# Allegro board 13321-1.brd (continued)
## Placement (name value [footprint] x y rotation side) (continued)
PG4404  GAP-CLOSE-PWR-3-GP  [GAP-CLOSE-PWR-3]  73.41 26.76 180 bottom
PG4405  GAP-CLOSE-PWR-3-GP  [GAP-CLOSE-PWR-3]  76.71 26.76 0 bottom
PG4406  GAP-CLOSE-PWR-3-GP  [GAP-CLOSE-PWR-3]  44.7 26.76 90 bottom
PG4407  GAP-CLOSE-PWR-3-GP  [GAP-CLOSE-PWR-3]  73.41 25.62 180 bottom
PG4408  GAP-CLOSE-PWR-3-GP  [GAP-CLOSE-PWR-3]  42.16 7.71 270 top
PG4532  GAP-CLOSE-PWR-3-GP  [GAP-CLOSE-PWR-3]  24.38 86.71 270 bottom
PG4535  GAP-CLOSE-PWR-3-GP  [GAP-CLOSE-PWR-3]  39.12 87.72 0 bottom
PG4707  GAP-CLOSE-PWR-3-GP  [GAP-CLOSE-PWR-3]  50.67 63.09 90 bottom
PG4708  GAP-CLOSE-PWR-3-GP  [GAP-CLOSE-PWR-3]  50.67 58.26 270 bottom
PG4801  GAP-CLOSE-PWR-3-GP  [GAP-CLOSE-PWR-3]  53.72 83.91 0 bottom
PG4901  -  [GAP-CLOSE-PWR]  141.35 39.34 90 bottom
PG4902  -  [GAP-CLOSE-PWR]  137.67 57.12 90 bottom
PG4903  -  [GAP-CLOSE-PWR]  139.83 39.34 90 bottom
PG4904  -  [GAP-CLOSE-PWR]  139.95 57.12 90 bottom
PG4905  -  [GAP-CLOSE-PWR]  140.72 57.12 90 bottom
PG4906  -  [GAP-CLOSE-PWR]  140.59 39.34 90 bottom
PG4907  -  [GAP-CLOSE-PWR]  142.11 39.34 90 bottom
PG4908  -  [GAP-CLOSE-PWR]  139.19 57.12 90 bottom
PG4909  -  [GAP-CLOSE-PWR]  138.43 57.12 90 bottom
PG4917  -  [GAP-CLOSE-PWR]  135.51 76.42 90 top
PG4918  -  [GAP-CLOSE-PWR]  134.75 76.42 90 top
PG5101  -  [GAP-CLOSE-PWR]  56.64 89.12 90 bottom
PL4401  COIL-2D2UH-11-GP  [L11510030H158]  63.25 27.91 270 bottom
PL4501  IND-3D3UH-57GP  [L736630H119]  28.45 81.37 0 bottom
PL4503  COIL-4D7UH-33-GP  [L7066-1830-UH119]  37.47 81.25 180 bottom
PL4701  IND-D22UH-46-GP  [L109100-2430-UH158]  50.67 60.67 180 bottom
PL4801  IND-D68UH-40-GP  [L4947-1015H119]  52.83 83.91 270 bottom
PL4901  IND-D68UH-40-GP  [L4947-1015H119]  139.7 49.88 0 bottom
PQ4201  FDV301N-NL-GP  [SOT23DGS2D4H44]  37.72 97.25 270 top
PQ4202  CH3904PT-GP  [SOT23CBE2D6H46]  37.72 101.06 90 top
PQ4401  2N7002K-2-GP  [SOT23DGS2D4H44]  27.69 6.06 180 top
PQ4405  2N7002KDW-GP  [SOT-363H44]  38.48 4.54 90 top
PQ4406  2N7002K-2-GP  [SOT23DGS2D4H44]  40.64 10.38 180 bottom
PQ4407  2N7002KDW-GP  [SOT-363H44]  40.16 25.83 270 top
PQ4408  MMBT3906-4-GP  [SOT23CBE2D4H44]  23.5 6.06 180 top
PQ4411  2N7002KDW-GP  [SOT-363H44]  33.4 3.52 90 bottom
PQ4413  2N7002KDW-GP  [SOT-363H44]  38.48 4.54 270 bottom
PR4202  15KR2F-GP  [R402H16]  35.31 99.36 180 top
PR4203  10KR2J-3-GP  [R402H16]  35.31 96.61 180 top
PR4204  2K2R2J-2-GP  [R402H16]  42.29 98.52 270 top
PR4205  33R2J-2-GP  [R402H16]  41.91 97.12 180 top
PR4206  33R2J-2-GP  [R402H16]  41.02 97.12 0 top
PR4207  240KR3-GP  [R603H22]  44.32 29.69 180 bottom
PR4208  47KR3J-L-GP  [R603H22]  45.72 29.69 0 bottom
PR4209  100KR2J-1-GP  [R402H16]  35.31 102.08 0 top
PR4217  0R0603-PAD-2-GP-U  [0R0603-PAD-1-U]  17.27 92.8 180 top
PR4401  182KR2F-GP  [R402H16]  31.88 5.56 270 bottom
PR4402  75KR2F-GP  [R402H16]  31.5 8.35 180 bottom
PR4403  10R5J-GP  [R805H24]  35.56 18.26 90 top
PR4404  120KR2J-GP  [R402H16]  42.39 5.3 0 bottom
PR4405  100KR2F-L1-GP  [R402H16]  35.94 7.59 0 top
PR4406  0R0402-PAD-2-GP  [0R0402-PAD-1]  43.18 15.08 180 bottom
PR4407  6D8R2F-GP  [R402H16]  75.06 27.53 90 top
PR4408  20R3F-L-GP  [R603H22]  48.03 12.11 270 top
PR4409  1KR2F-3-GP  [R402H16]  46.99 13.18 90 top
PR4410  100KR2J-1-GP  [R402H16]  41.5 5.3 180 bottom
PR4411  47KR2F-GP  [R402H16]  36.96 11.52 0 top
PR4412  100KR2J-1-GP  [R402H16]  39.37 7.21 90 bottom
PR4413  0R2J-2-GP  [R402H16]  44.2 7.59 180 top
PR4414  3K3R2J-3-GP  [R402H16]  42.55 5.3 180 top
PR4415  0R2J-2-GP  [R402H16]  45.09 7.59 180 top
PR4416  100KR2J-1-GP  [R402H16]  26.29 8.48 270 top
PR4417  0R0402-PAD-2-GP  [0R0402-PAD-1]  47.75 15.08 90 top
PR4418  3K3R6J-GP  [R1206H28]  39.75 22.07 180 top
PR4419  0R2J-2-GP  [R402H16]  29.08 9.24 0 top
PR4420  75KR2F-GP  [R402H16]  37.59 2.51 270 bottom
PR4421  0R2J-2-GP  [R402H16]  36.96 15.08 0 top
PR4422  1M8R2J-L-GP  [R402H16]  31.75 3.14 0 top
PR4423  10KR2F-2-GP  [R402H16]  42.42 23.97 0 top
PR4424  100KR2F-L1-GP  [R402H16]  44.7 10.13 0 bottom
PR4425  0R3J-0-U-GP  [R603H22]  42.16 18.64 180 top
PR4426  D01R3721F-GP-U  [R3720H40]  45.21 24.61 270 bottom
PR4427  2D2R5F-2-GP  [R805H24]  54.36 28.54 270 top
PR4428  150KR2F-L-GP  [R402H16]  32.38 8.35 180 bottom
PR4429  100KR2J-1-GP  [R402H16]  38.35 9.37 180 bottom
PR4430  0R0402-PAD-2-GP  [0R0402-PAD-1]  37.47 12.79 270 top
PR4431  100KR2F-L1-GP  [R402H16]  43.81 10.13 0 bottom
PR4432  3K3R2J-3-GP  [R402H16]  43.43 5.3 180 top
PR4433  1MR2J-1-GP  [R402H16]  21.21 7.46 180 top
PR4434  0R0402-PAD-2-GP  [0R0402-PAD-1]  37.59 7.59 0 top
PR4435  100KR2J-1-GP  [R402H16]  42.8 22.57 270 top
PR4436  220KR2F-GP  [R402H16]  35.94 6.83 180 bottom
PR4437  100KR2J-1-GP  [R402H16]  35.05 6.83 0 bottom
PR4438  0R0402-PAD-2-GP  [0R0402-PAD-1]  47.75 16.1 90 top
PR4439  4K02R2F-GP  [R402H16]  37.47 13.68 90 top
PR4440  120KR2J-GP  [R402H16]  30.61 12.29 270 top
PR4441  100KR2F-L1-GP  [R402H16]  30.61 14.06 90 top
PR4442  412KR2F-GP  [R402H16]  32.38 14.06 270 top
PR4443  D01R2512F-3-GP  [R2512H32]  75.06 26.26 270 bottom
PR4444  287KR2F-GP  [R402H16]  36.58 9.62 90 top
PR4445  33KR2F-GP  [R402H16]  46.48 10.13 180 bottom
PR4446  20KR2F-L-GP  [R402H16]  77.72 30.57 180 top
PR4447  180KR2F-GP  [R402H16]  32.38 12.29 90 top
PR4448  0R2J-2-GP  [R402H16]  73.79 27.15 180 top
PR4449  100KR2J-1-GP  [R402H16]  46.48 11.91 180 bottom
PR4450  10KR2F-2-GP  [R402H16]  34.8 4.54 180 top
PR4451  680KR2F-GP  [R402H16]  44.83 3.52 90 top
PR4452  0R2J-2-GP  [R402H16]  77.72 28.8 180 top
PR4453  100KR2F-L1-GP  [R402H16]  28.32 12.29 90 top
PR4454  10R2F-L-GP  [R402H14]  76.33 27.15 180 top
PR4455  0R0402-PAD-2-GP  [0R0402-PAD-1]  41.53 5.3 0 top
PR4456  0R2J-2-GP  [R402H16]  36.83 10 0 bottom
PR4457  0R2J-2-GP  [R402H16]  41.78 3.02 0 bottom
PR4458  0R0402-PAD-2-GP  [0R0402-PAD-1]  32.77 13.3 180 bottom
PR4460  100KR2F-L1-GP  [R402H16]  29.08 11.02 0 top
PR4461  100KR2F-L1-GP  [R402H16]  30.61 13.18 90 top
PR4462  0R0402-PAD-2-GP  [0R0402-PAD-1]  42.93 3.52 90 top
PR4463  0R2J-2-GP  [R402H16]  41.15 3.52 90 top
PR4464  0R2J-2-GP  [R402H16]  26.8 3.65 90 top
PR4465  316KR2F-GP  [R402H16]  32.38 13.18 270 top
PR4466  0R0402-PAD-2-GP  [0R0402-PAD-1]  29.46 2.76 270 top
PR4467  0R0402-PAD-2-GP  [0R0402-PAD-1]  40.26 7.59 0 top
PR4468  150KR2F-L-GP  [R402H16]  45.59 10.13 0 bottom
PR4469  0R0402-PAD-2-GP  [0R0402-PAD-1]  41.15 7.59 180 top
PR4470  100KR2J-1-GP  [R402H16]  47.75 18.13 0 top
PR4471  100KR2J-1-GP  [R402H16]  49.02 17.87 90 top
PR4501  0R2J-2-GP  [R402H16]  33.15 62.45 90 bottom
PR4502  200R2J-L1-GP  [R402H16]  31.01 64.36 270 top
PR4504  0R0402-PAD-2-GP  [0R0402-PAD-1]  32.64 64.36 270 bottom
PR4506  0R0402-PAD-2-GP  [0R0402-PAD-1]  40.01 63.47 270 top
PR4512  6K65R2F-GP  [R402H16]  38.73 62.07 180 top
PR4515  0R0402-PAD-2-GP  [0R0402-PAD-1]  30.86 64.36 270 bottom
PR4517  34K8R2F-1-GP  [R402H16]  40.01 62.66 90 top
PR4523  10KR2F-2-GP  [R402H16]  36.96 62.07 0 top
PR4524  1D5R3-GP  [R603H22]  31.37 66.77 270 top
PR4525  0R2J-2-GP  [R402H16]  33.15 61.61 270 bottom
PR4526  9K76R2F-1-GP  [R402H16]  33.96 62.07 0 top
PR4527  15KR2F-GP  [R402H16]  32.26 61.69 180 top
PR4528  1D5R3-GP  [R603H22]  40.26 66.77 270 top
PR4529  2D2R5F-2-GP  [R805H24]  29.08 75.79 0 top
PR4530  0R2J-2-GP  [R402H16]  33.15 63.34 270 bottom
PR4531  49K9R2F-L-GP  [R402H16]  31.01 62.93 270 top
PR4532  0R0402-PAD-2-GP  [0R0402-PAD-1]  34.77 62.07 180 top
PR4533  2D2R5F-2-GP  [R805H24]  36.32 74.9 0 top
PR4534  100KR2J-1-GP  [R402H16]  40.01 64.36 270 top
PR4535  0R2J-2-GP  [R402H16]  38.23 60.8 270 top
PR4601  150KR2F-L-GP  [R402H16]  42.29 54.96 180 top
PR4602  NTC-100K-10-GP-U  [NTC-402H22-U]  55.12 70.83 0 bottom
PR4603  75R2F-2-GP  [R402H16]  42.29 54.96 180 bottom
PR4604  499KR2F-1-GP  [R402H16]  43.18 54.96 180 bottom
PR4605  71K5R2F-1-GP  [R402H16]  44.07 54.96 180 bottom
PR4607  75KR2F-GP  [R402H16]  43.18 54.96 180 top
PR4608  39KR2F-GP  [R402H16]  44.07 54.96 180 top
PR4609  56KR2F-GP  [R402H16]  41.35 55.59 180 top
PR4610  392KR2F-GP  [R402H16]  40.97 54.32 90 top
PR4611  75R2F-2-GP  [R402H16]  41.4 54.96 180 bottom
PR4612  39KR2F-GP  [R402H16]  38.1 54.96 0 top
PR4613  10R3J-3-GP  [R603H22]  36.96 52.55 90 top
PR4614  2KR2F-3-GP  [R402H16]  47.75 49.12 270 top
PR4615  0R0402-PAD-2-GP  [0R0402-PAD-1]  45.97 52.8 90 top
PR4616  0R0402-PAD-2-GP  [0R0402-PAD-1]  40.39 47.21 90 bottom
PR4617  0R0402-PAD-2-GP  [0R0402-PAD-1]  39.5 49.5 90 bottom
PR4618  10R3J-3-GP  [R603H22]  47.24 47.72 90 top
PR4619  10KR2F-2-GP  [R402H16]  36.83 46.32 0 top
PR4620  3K4R2F-GP  [R402H16]  37.72 45.43 0 top
PR4621  130R2F-1-GP  [R402H16]  43.94 45.69 90 bottom
PR4622  54D9R2F-L1-GP  [R402H16]  43.94 43.91 90 bottom
PR4623  130R2F-1-GP  [R402H16]  43.94 44.8 90 bottom
PR4624  10R3J-3-GP  [R603H22]  40.51 44.04 270 top
PR4625  0R0402-PAD-2-GP  [0R0402-PAD-1]  45.97 50.01 90 top
PR4626  0R2J-2-GP  [R402H16]  45.97 51.91 90 top
PR4627  4K75R2F-1-GP  [R402H16]  36.45 47.59 270 top
PR4701  2D2R5F-2-GP  [R805H24]  48.51 68.42 90 bottom
PR4702  0R0402-PAD-2-GP  [0R0402-PAD-1]  55.24 73.75 180 bottom
PR4703  2D2R3F-L-GP  [R603H24]  52.7 77.56 0 bottom
PR4704  2K32R2F-1-GP  [R402H16]  44.2 61.44 90 bottom
PR4705  16K2R2F-GP  [R402H16]  43.56 59.15 180 bottom
PR4706  2K94R2F-GP  [R402H16]  44.2 60.55 270 bottom
PR4707  NTC-10K-26-GP-U  [NTC-402H22-U]  44.58 59.15 180 bottom
PR4801  0R3J-0-U-GP  [R603H22]  43.56 85.31 270 top
PR4802  0R0402-PAD-2-GP  [0R0402-PAD-1]  46.48 87.98 0 bottom
PR4803  1MR2J-L3-GP  [R402H16]  48.26 88.61 0 bottom
PR4804  0R0402-PAD-2-GP  [0R0402-PAD-1]  49.15 88.61 180 bottom
PR4805  100KR2F-L3-GP  [R402H16]  43.81 87.98 0 bottom
PR4806  75KR2F-GP  [R402H16]  44.7 87.98 180 bottom
PR4807  0R0402-PAD-2-GP  [0R0402-PAD-1]  41.15 87.98 0 bottom
PR4901  2D2R3F-L-GP  [R603H24]  137.79 43.66 90 top
PR4902  0R0402-PAD-2-GP  [0R0402-PAD-1]  139.19 41.12 0 top
PR4903  150KR2F-L-GP  [R402H16]  135.76 42.77 270 bottom
PR4904  120KR2F-L-GP  [R402H16]  135.76 43.66 90 bottom
PR4905  0R0402-PAD-2-GP  [0R0402-PAD-1]  135.76 47.34 270 bottom
PR4906  0R0402-PAD-2-GP  [0R0402-PAD-1]  135.76 45.56 270 bottom
PR4907  0R0402-PAD-2-GP  [0R0402-PAD-1]  135.76 45.56 90 top
PR4909  10KR2J-3-GP  [R402H16]  135 82.9 180 bottom
PR4910  1KR2J-1-GP  [R402H16]  135.76 46.45 90 top
PR4914  0R0402-PAD-2-GP  [0R0402-PAD-1]  138.68 70.96 180 top
PR4917  0R2J-2-GP  [R402H16]  138.05 82.77 270 bottom
PR4918  0R2J-2-GP  [R402H16]  138.05 81.88 270 bottom
PR4925  0R2J-2-GP  [R402H16]  135.89 82.9 180 bottom
PR4926  0R2J-2-GP  [R402H16]  136.78 82.9 180 bottom
PR5101  0R0402-PAD-2-GP  [0R0402-PAD-1]  49.15 90.39 0 bottom
PT4501  ST220U6D3VBM-3-GP  [CT3528H79]  35.81 87.72 90 bottom
PT4502  ST220U6D3VBM-3-GP  [CT3528H79]  28.96 87.72 270 bottom
PT4702  ST33U25VDM-2-GP  [CT7343H119]  40.77 38.83 90 bottom
PU4201  SI7121DN-T1-GE3-GP  [PPAK-8P-2H45]  39.5 27.65 0 bottom
PU4401  BQ24770RUYR-1-GP  [QFN28-G2D7H32]  42.16 13.3 90 top
PU4402  LM393PWR-GP  [TSOIC8H48]  31.54 7.95 180 top
PU4403  SI7121DN-T1-GE3-GP  [PPAK-8P-2H45]  85.98 24.73 90 bottom
PU4404  INA199A1-GP  [SC70-6H44]  74.55 30.45 270 top
PU4405  SI7121DN-T1-GE3-GP  [PPAK-8P-2H45]  39.75 23.46 270 bottom
PU4406  FDMS3600-02-RJK0215-COLAY-GP  [PPAK-8P-G5324H44-COLAY]  53.09 27.27 180 bottom
PU4501  CSD87381P-GP  [SON5Z3025H18]  29.08 74.64 90 bottom
PU4502  CSD87381P-GP  [SON5Z3025H18]  36.32 74.64 90 bottom
PU4503  TPS51225RUKR-GP  [QFN20-G1D75H32]  35.81 65.5 180 top
PU4601  TPS51624RSMR-GP-U  [QFN32J4-G2D9-U1H40]  41.27 50.13 270 top
PU4701  CSD97374Q4M-GP-U1  [DFN8J4535-G4122-U1H40]  51.82 72.74 0 bottom
PU4801  SY8208DQNC-GP-U  [QFN10M3-G4P-UH34]  44.89 84.2 90 bottom
PU4901  SY8206DQNC-GP-U  [QFN10M3-G4P-UH34]  139.45 44.29 180 bottom
PU4902  APL5338XAI-TRG-GP  [MSOP10-G2D5H44]  136.78 77.18 180 bottom
PU5101  TLV70215DBVR-GP  [SOT-23-5H58]  52.83 89.63 90 bottom
Q1201  FDV301N-NL-GP  [SOT23DGS2D4H44]  149.86 28.29 90 bottom
Q1202  2N7002K-2-GP  [SOT23DGS2D4H44]  136.53 85.69 180 bottom
Q1701  2N7002KDW-GP  [SOT-363H44]  98.42 94.2 0 top
Q1801  2N7002KDW-GP  [SOT-363H44]  106.55 94.2 0 top
Q1901  2N7002K-2-GP  [SOT23DGS2D4H44]  95.76 102.2 180 bottom
Q2401  2N7002K-2-GP  [SOT23DGS2D4H44]  66.17 37.56 270 bottom
Q2402  DMP2130L-7-GP  [SOT23DGS2D4H48]  135.64 37.81 180 bottom
Q2403  2N7002K-2-GP  [SOT23DGS2D4H44]  135.64 34 180 bottom
Q2404  MMBT3906-4-GP  [SOT23CBE2D4H44]  47.37 5.94 0 top
Q2505  2N7002K-2-GP  [SOT23DGS2D4H44]  143 64.86 90 top
Q2601  2N7002KDW-GP  [SOT-363H44]  103.5 94.2 0 top
Q2602  2N7002K-2-GP  [SOT23DGS2D4H44]  100.2 30.32 270 bottom
Q2603  CH3904PT-GP  [SOT23CBE2D6H46]  100.46 101.69 90 bottom
Q2901  2N7002K-2-GP  [SOT23DGS2D4H44]  21.97 31.34 0 bottom
Q3601  2N7002KDW-GP  [SOT-363H44]  47.12 94.07 90 top
Q5401  CH3904PT-GP  [SOT23CBE2D6H46]  19.43 71.34 0 top
Q5402  2N7002KDW-GP  [SOT-363H44]  18.16 87.6 180 top
Q5403  2N7002K-2-GP  [SOT23DGS2D4H44]  19.56 75.41 90 top
Q5404  2N7002K-2-GP  [SOT23DGS2D4H44]  19.3 67.46 180 top
Q6201  DDTA144VCA-7-F-GP  [SOT23CBE2D4H44]  145.03 29.3 0 bottom
Q6202  P8503BMG-GP  [SOT23DGS2D8H56]  23.37 10.51 270 top
Q6203  DMP2130L-7-GP  [SOT23DGS2D4H48]  104.39 24.35 90 bottom
Q6204  2N7002KDW-GP  [SOT-363H44]  123.83 23.84 270 bottom
Q6205  2N7002K-2-GP  [SOT23DGS2D4H44]  123.83 20.54 270 bottom
Q6701  2N7002KDW-GP  [SOT-363H44]  154.05 17.75 180 bottom
R401  62R2J-GP  [R402H16]  68.96 38.45 90 bottom
R402  51R2J-2-GP  [R402H16]  67.18 42 270 top
R403  56R2J-4-GP  [R402H16]  73.91 36.8 270 bottom
R404  0R0402-PAD-2-GP  [0R0402-PAD-1]  128.14 42 90 top
R405  10KR2J-3-GP  [R402H16]  66.04 43.15 180 bottom
R406  51R2J-2-GP  [R402H16]  67.18 41.12 270 top
R407  200R2F-L-GP  [R402H16]  90.42 44.8 0 top
R408  121R2F-GP  [R402H16]  92.71 45.69 90 top
R409  100R2F-L1-GP-U  [R402H14]  93.85 40.73 0 top
R410  470R2J-2-GP  [R402H16]  96.39 71.21 90 top
R601  49D9R2F-GP  [R402H16]  82.3 41.75 270 top
R602  49D9R2F-GP  [R402H16]  96.52 73.12 90 top
R603  8K2R2F-1-GP  [R402H16]  67.56 73.37 0 bottom
R604  1KR2J-1-GP  [R402H16]  86.23 37.81 180 top
R605  1KR2J-1-GP  [R402H16]  82.93 43.66 0 top
R606  49D9R2F-GP  [R402H16]  81.79 68.67 270 top
R701  43R2J-GP  [R402H16]  76.96 35.91 0 bottom
R702  100R2F-L1-GP-U  [R402H14]  74.8 43.02 0 top
R703  75R2F-2-GP  [R402H16]  75.69 36.04 90 bottom
R704  130R2F-1-GP  [R402H16]  75.69 36.92 90 bottom
R705  150R2J-L1-GP-U  [R402H16]  73.15 38.19 0 bottom
R706  10KR2J-3-GP  [R402H16]  61.59 43.15 0 bottom
R707  100KR2F-L1-GP  [R402H16]  63.37 44.93 180 bottom
R709  47KR2F-GP  [R402H16]  64.26 44.93 0 bottom
R710  10KR2J-3-GP  [R402H16]  63.37 43.15 0 bottom
R711  0R0603-PAD-2-GP-U  [0R0603-PAD-1-U]  83.57 65.75 90 top
R712  47KR2F-GP  [R402H16]  64.26 43.15 180 bottom
R713  100KR2F-L1-GP  [R402H16]  62.48 43.15 0 bottom
R801  24D9R2F-L-GP  [R402H16]  72.77 70.07 270 top
R901  100R2F-L1-GP-U  [R402H14]  75.69 43.02 180 top
R1101  0R0805-PAD-2-GP-U  [0R0805-PAD-1-U]  63.63 72.48 90 top
R1102  0R0603-PAD-2-GP-U  [0R0603-PAD-1-U]  85.85 70.58 0 top
R1103  0R0603-PAD-2-GP-U  [0R0603-PAD-1-U]  109.6 68.67 0 top
R1104  0R0603-PAD-2-GP-U  [0R0603-PAD-1-U]  82.42 73.5 90 top
R1105  0R0805-PAD-2-GP-U  [0R0805-PAD-1-U]  61.98 74.52 90 top
R1201  0R0402-PAD-2-GP  [0R0402-PAD-1]  127.51 94.96 0 top
R1202  0R0402-PAD-2-GP  [0R0402-PAD-1]  126.62 94.96 0 top
R1204  2MR2-GP  [R402H16]  150.62 30.57 270 bottom
R1205  0R0402-PAD-2-GP  [0R0402-PAD-1]  147.45 28.54 0 bottom
R1206  66D5R2F-GP  [R402H16]  127.76 74.9 0 top
R1207  66D5R2F-GP  [R402H16]  128.65 74.9 0 top
R1208  220KR2J-L2-GP  [R402H16]  148.84 30.57 270 bottom
R1501  0R0402-PAD-2-GP  [0R0402-PAD-1]  81.41 106.27 0 top
R1601  3KR2F-GP  [R402H16]  69.72 65.37 180 top
R1602  22D6R2F-L1-GP  [R402H16]  89.15 76.17 90 top
R1701  10KR2J-3-GP  [R402H16]  75.44 89.88 180 top
R1702  1KR2J-1-GP  [R402H16]  100.84 95.6 90 top
R1703  1KR2J-1-GP  [R402H16]  103.12 90.39 270 top
R1704  0R2J-2-GP  [R402H16]  100.84 88.11 180 top
R1705  0R2J-2-GP  [R402H16]  101.09 92.8 270 top
R1706  0R0402-PAD-2-GP  [0R0402-PAD-1]  97.79 91.03 90 top
R1707  0R0402-PAD-2-GP  [0R0402-PAD-1]  99.06 91.53 180 top
R1708  0R2J-2-GP  [R402H16]  90.68 91.79 0 top
R1709  0R0402-PAD-2-GP  [0R0402-PAD-1]  70.99 87.6 180 top
R1710  0R0402-PAD-2-GP  [0R0402-PAD-1]  74.17 91.79 0 bottom
R1713  0R0402-PAD-2-GP  [0R0402-PAD-1]  81.15 92.42 0 top
R1714  8K2R2F-1-GP  [R402H16]  69.09 87.34 270 top
R1715  100KR2J-1-GP  [R402H16]  81.15 94.2 180 top
R1717  10KR2J-3-GP  [R402H16]  85.85 97 90 top
R1718  0R0402-PAD-2-GP  [0R0402-PAD-1]  101.73 88.11 180 top
R1720  330KR2J-L1-GP  [R402H16]  100.33 80.1 180 top
R1721  330KR2J-L1-GP  [R402H16]  99.06 79.72 270 top
R1724  10KR2J-3-GP  [R402H16]  83.82 92.42 0 top
R1725  100KR2F-L1-GP  [R402H16]  100.84 89.88 0 top
R1726  10KR2J-3-GP  [R402H16]  97.66 96.49 270 top
R1727  100KR2J-1-GP  [R402H16]  96.39 96.87 0 top
R1728  0R2J-2-GP  [R402H16]  80.01 112.49 270 top
R1729  0R0402-PAD-2-GP  [0R0402-PAD-1]  80.39 110.33 180 top
R1801  0R0402-PAD-2-GP  [0R0402-PAD-1]  101.73 69.69 270 top
R1802  1MR2J-1-GP  [R402H16]  63.63 67.28 0 bottom
R1803  3KR2F-GP  [R402H16]  69.34 67.02 270 top
R1804  0R2J-2-GP  [R402H16]  92.84 69.06 180 top
R1805  33R2J-2-GP  [R402H16]  92.84 70.83 0 top
R1806  33R2J-2-GP  [R402H16]  137.41 100.42 0 bottom
R1807  0R0402-PAD-2-GP  [0R0402-PAD-1]  74.55 88.87 270 bottom
R1808  0R0402-PAD-2-GP  [0R0402-PAD-1]  136.53 100.42 0 bottom
R1809  0R0402-PAD-2-GP  [0R0402-PAD-1]  135.64 100.42 0 bottom
R1810  0R0402-PAD-2-GP  [0R0402-PAD-1]  63.63 65.5 180 bottom
R1811  0R0402-PAD-2-GP  [0R0402-PAD-1]  74.55 90.49 270 bottom
R1812  0R0402-PAD-2-GP  [0R0402-PAD-1]  74.55 89.68 270 bottom
R1901  1MR2J-1-GP  [R402H16]  101.6 79.72 270 top
R1902  10KR2J-3-GP  [R402H16]  98.04 101.69 0 bottom
R1903  330KR2J-L1-GP  [R402H16]  103.25 80.61 90 top
R1904  0R0402-PAD-2-GP  [0R0402-PAD-1]  66.17 74.64 90 bottom
R1905  10KR2J-3-GP  [R402H16]  68.58 86.84 270 bottom
R1906  3KR2F-GP  [R402H16]  66.17 75.53 90 bottom
R1907  33R2J-2-GP  [R402H16]  101.73 74.39 270 top
R1908  0R0402-PAD-2-GP  [0R0402-PAD-1]  101.73 75.53 270 top
R1909  1KR2J-1-GP  [R402H16]  101.73 76.68 270 top
R1911  33R2J-2-GP  [R402H16]  101.73 73.5 270 top
R1912  33R2J-2-GP  [R402H16]  103.5 76.17 270 top
R1913  330KR2J-L1-GP  [R402H16]  105.66 80.61 270 top
R1915  10MR2J-L-GP  [R402H16]  94.87 91.56 0 bottom
R1916  51R2J-2-GP  [R402H16]  80.52 40.23 270 top
R1917  51R2J-2-GP  [R402H16]  80.52 38.96 270 top
R1918  51R2J-2-GP  [R402H16]  82.3 40.23 270 top
R1919  1KR2J-1-GP  [R402H16]  82.3 38.96 270 top
R1920  51R2J-2-GP  [R402H16]  84.45 43.78 180 top
R2001  10KR2J-3-GP  [R402H16]  84.71 88.36 0 top
R2002  0R0402-PAD-2-GP  [0R0402-PAD-1]  83.19 90.14 0 top
R2003  49D9R2F-GP  [R402H16]  94.74 73.12 270 top
R2004  10KR2J-3-GP  [R402H16]  83.82 88.36 0 top
R2005  0R2J-2-GP  [R402H16]  98.3 83.53 270 top
R2006  1KR2J-1-GP  [R402H16]  69.09 88.61 270 bottom
R2007  100KR2J-1-GP  [R402H16]  57.15 77.95 180 top
R2008  0R0402-PAD-2-GP  [0R0402-PAD-1]  71.88 86.58 180 top
R2009  0R0402-PAD-2-GP  [0R0402-PAD-1]  85.34 90.52 90 top
R2010  0R0402-PAD-2-GP  [0R0402-PAD-1]  81.28 88.36 0 top
R2011  1KR2J-1-GP  [R402H16]  63.5 84.42 90 bottom
R2012  1KR2J-1-GP  [R402H16]  64.64 79.85 90 top
R2013  100KR2J-1-GP  [R402H16]  64.64 80.74 270 top
R2014  1KR2J-1-GP  [R402H16]  82.04 92.42 0 top
R2015  0R0402-PAD-2-GP  [0R0402-PAD-1]  82.55 88.36 0 top
R2016  0R0402-PAD-2-GP  [0R0402-PAD-1]  80.64 90.14 0 top
R2017  10KR2J-3-GP  [R402H16]  85.6 88.36 0 top
R2018  1KR2J-1-GP  [R402H16]  61.21 41.75 270 bottom
R2019  0R0402-PAD-2-GP  [0R0402-PAD-1]  85.34 89.63 90 top
R2020  0R0402-PAD-2-GP  [0R0402-PAD-1]  80.01 88.36 0 top
R2021  10KR2J-3-GP  [R402H16]  87.66 89.07 270 top
R2022  10KR2J-3-GP  [R402H16]  82.93 92.42 0 top
R2023  10KR2J-3-GP  [R402H16]  69.09 87.72 270 bottom
R2024  10KR2J-3-GP  [R402H16]  71.25 83.15 90 top
R2025  10KR2J-3-GP  [R402H16]  71.25 84.04 90 top
R2026  0R2J-2-GP  [R402H16]  77.72 94.58 270 top
R2027  0R2J-2-GP  [R402H16]  88.65 100.04 90 top
R2028  0R0402-PAD-2-GP  [0R0402-PAD-1]  81.92 90.14 0 top
R2101  0R0402-PAD-2-GP  [0R0402-PAD-1]  90.42 69.18 180 top
R2102  0R0603-PAD-2-GP-U  [0R0603-PAD-1-U]  108.97 70.58 90 top
R2103  0R0402-PAD-2-GP  [0R0402-PAD-1]  71.25 82.26 270 top
R2105  0R0402-PAD-2-GP  [0R0402-PAD-1]  71.88 78.2 90 top
R2108  0R0603-PAD-2-GP-U  [0R0603-PAD-1-U]  108.97 71.85 270 top
R2110  5D1R2F-GP  [R402H16]  88.01 69.18 0 top
R2112  0R0402-PAD-2-GP  [0R0402-PAD-1]  80.26 73.63 90 top
R2114  0R5J-5-GP  [R805H24]  60.33 72.23 270 bottom
R2117  0R0402-PAD-2-GP  [0R0402-PAD-1]  68.83 70.58 90 top
R2118  0R0402-PAD-2-GP  [0R0402-PAD-1]  80.77 66.77 180 top
R2122  0R0805-PAD-2-GP-U  [0R0805-PAD-1-U]  60.71 72.48 90 top
R2123  0R2J-2-GP  [R402H16]  57.15 76.17 0 top
R2401  0R0402-PAD-2-GP  [0R0402-PAD-1]  144.02 47.85 90 top
R2402  0R0603-PAD-2-GP-U  [0R0603-PAD-1-U]  160.53 60.67 180 top
R2403  2D2R3-1-U-GP  [R603H22]  154.81 59.66 180 top
R2404  64K9R2F-1-GP  [R402H16]  164.59 59.4 270 top
R2405  10KR2F-2-GP  [R402H16]  166.37 56.36 0 top
R2406  100KR2F-L1-GP  [R402H16]  162.81 59.4 270 top
R2407  100KR2F-L1-GP  [R402H16]  165.48 56.36 180 top
R2408  0R0402-PAD-1-GP  [0R0402-PAD]  145.03 36.8 270 top
R2409  0R0402-PAD-1-GP  [0R0402-PAD]  148.84 44.8 270 bottom
R2412  100KR2J-1-GP  [R402H16]  161.8 57.63 270 top
R2413  100KR2J-1-GP  [R402H16]  162.81 34 270 top
R2414  10KR2J-3-GP  [R402H16]  164.34 32.86 0 top
R2415  10KR2J-3-GP  [R402H16]  144.02 40.86 270 top
R2416  0R0402-PAD-2-GP  [0R0402-PAD-1]  144.02 49.62 270 top
R2417  0R0402-PAD-2-GP  [0R0402-PAD-1]  74.8 99.79 90 top
R2418  10KR2J-3-GP  [R402H16]  165.23 32.86 0 top
R2419  33R2J-2-GP  [R402H16]  166.24 51.28 270 top
R2420  33R2J-2-GP  [R402H16]  141.6 86.84 180 bottom
R2421  100KR2J-1-GP  [R402H16]  148.21 40.35 180 bottom
R2422  33R2J-2-GP  [R402H16]  139.83 86.84 180 bottom
R2423  33R2J-2-GP  [R402H16]  138.94 86.84 180 bottom
R2424  0R2J-2-GP  [R402H16]  47.37 3.52 90 top
R2425  330KR2J-L1-GP  [R402H16]  166.24 54.07 90 top
R2426  0R0402-PAD-2-GP  [0R0402-PAD-1]  151.51 58.39 0 top
R2427  0R0402-PAD-2-GP  [0R0402-PAD-1]  166.24 54.96 270 top
R2428  0R0402-PAD-2-GP  [0R0402-PAD-1]  155.96 58.39 180 top
R2429  43R2J-GP  [R402H16]  144.15 35.65 180 bottom
R2430  0R0402-PAD-2-GP  [0R0402-PAD-1]  164.34 35.4 180 top
R2431  330KR2J-L1-GP  [R402H16]  138.3 37.18 270 bottom
R2432  1KR2J-1-GP  [R402H16]  164.85 37.18 0 top
R2433  20KR2F-L-GP  [R402H16]  138.3 33.62 270 bottom
R2434  0R2J-2-GP  [R402H16]  137.92 38.83 0 bottom
R2435  0R0402-PAD-2-GP  [0R0402-PAD-1]  158.75 57.24 0 top
R2436  10KR2J-3-GP  [R402H16]  144.02 46.96 90 top
R2437  0R0402-PAD-2-GP  [0R0402-PAD-1]  150.24 61.18 90 top
R2438  0R2J-2-GP  [R402H16]  63.88 38.19 180 bottom
R2439  10KR2J-3-GP  [R402H16]  46.35 8.22 90 top
R2440  0R0402-PAD-2-GP  [0R0402-PAD-1]  62.99 38.7 0 bottom
R2441  0R0402-PAD-2-GP  [0R0402-PAD-1]  154.94 44.16 90 bottom
R2442  100KR2J-1-GP  [R402H16]  144.02 44.54 270 top
R2443  10KR2J-3-GP  [R402H16]  149.61 43.91 90 bottom
R2444  0R0402-PAD-2-GP  [0R0402-PAD-1]  153.16 44.16 90 bottom
R2445  100KR2J-1-GP  [R402H16]  152.4 58.39 180 top
R2446  10KR2J-3-GP  [R402H16]  160.15 35.91 0 top
R2447  100KR2J-1-GP  [R402H16]  151.38 44.16 90 bottom
R2448  10KR2J-3-GP  [R402H16]  147.83 43.91 270 bottom
R2449  1KR2J-1-GP  [R402H16]  161.04 35.91 180 top
R2450  100KR2J-1-GP  [R402H16]  152.02 59.78 90 top
R2451  10KR2J-3-GP  [R402H16]  147.7 33.62 0 top
R2452  10KR2J-3-GP  [R402H16]  147.32 40.35 0 bottom
R2453  0R0402-PAD-2-GP  [0R0402-PAD-1]  147.7 33.62 180 bottom
R2454  10KR2J-3-GP  [R402H16]  145.03 35.91 270 top
R2455  100KR2J-1-GP  [R402H16]  152.02 61.18 90 top
R2457  0R0402-PAD-2-GP  [0R0402-PAD-1]  146.81 36.16 90 top
R2501  4K7R2J-2-GP  [R402H16]  166.24 48.86 270 top
R2504  10MR2J-L-GP  [R402H16]  142.49 67.15 270 top
R2601  0R0402-PAD-2-GP  [0R0402-PAD-1]  103.38 31.21 180 bottom
R2602  0R2J-2-GP  [R402H16]  103.38 29.43 180 bottom
R2603  7K5R2F-1-GP  [R402H16]  80.01 58.64 180 top
R2604  7K5R2F-1-GP  [R402H16]  83.06 54.83 90 top
R2607  2KR2F-3-GP  [R402H16]  108.46 27.15 270 bottom
R2608  24K3R2F-1-GP  [R402H16]  95.89 87.72 0 top
R2609  10R2F-L-GP  [R402H14]  96.7 87.72 0 top
R2610  NTC-100K-8-GP  [NTC-603H38]  96.01 85.44 0 top
R2611  0R0402-PAD-2-GP  [0R0402-PAD-1]  157.99 59.91 90 top
R2612  0R0402-PAD-2-GP  [0R0402-PAD-1]  139.45 69.06 270 bottom
R2701  0R0402-PAD-2-GP  [0R0402-PAD-1]  30.1 27.53 270 top
R2703  0R0603-PAD-2-GP-U  [0R0603-PAD-1-U]  24.77 34.64 0 bottom
R2704  0R0805-PAD-2-GP-U  [0R0805-PAD-1-U]  28.19 17.62 270 top
R2705  0R0402-PAD-2-GP  [0R0402-PAD-1]  21.79 16.6 180 top
R2706  0R0603-PAD-2-GP-U  [0R0603-PAD-1-U]  21.59 26.64 270 bottom
R2707  20KR2F-L-GP  [R402H16]  25.98 31.34 180 top
R2708  0R0402-PAD-2-GP  [0R0402-PAD-1]  27.69 21.18 0 bottom
R2709  200KR2F-L-GP  [R402H16]  26.8 32.1 180 top
R2710  0R2J-2-GP  [R402H16]  22.61 16.6 180 top
R2711  100KR2J-1-GP  [R402H16]  17.02 27.78 0 top
R2712  0R2J-2-GP  [R402H16]  24.64 34.64 180 top
R2714  0R0402-PAD-2-GP  [0R0402-PAD-1]  28.96 21.68 90 bottom
R2716  0R2J-2-GP  [R402H16]  29.84 22.57 90 bottom
R2717  1KR2J-1-GP  [R402H16]  30.1 29.3 270 top
R2718  0R0402-PAD-2-GP  [0R0402-PAD-1]  30.1 25.75 270 top
R2719  0R0402-PAD-2-GP  [0R0402-PAD-1]  30.1 23.97 270 top
R2720  0R2J-2-GP  [R402H16]  30.1 24.86 270 top
R2722  100KR2J-1-GP  [R402H16]  27.3 29.69 90 top
R2901  0R0603-PAD-2-GP-U  [0R0603-PAD-1-U]  18.03 15.84 90 bottom
R2902  0R0603-PAD-2-GP-U  [0R0603-PAD-1-U]  18.03 14.57 90 bottom
R2903  0R0603-PAD-2-GP-U  [0R0603-PAD-1-U]  17.91 6.83 270 top
R2904  0R0603-PAD-2-GP-U  [0R0603-PAD-1-U]  17.91 8.1 270 top
R2905  100KR2J-1-GP  [R402H16]  21.34 33.62 270 bottom
R2906  0R0603-PAD-2-GP-U  [0R0603-PAD-1-U]  17.53 21.81 180 bottom
R2907  0R0603-PAD-2-GP-U  [0R0603-PAD-1-U]  21.72 18.13 90 bottom
R2908  10R2F-L-GP  [R402H14]  17.53 23.46 270 top
R2909  0R0603-PAD-2-GP-U  [0R0603-PAD-1-U]  18.41 34.26 0 bottom
R2910  10R2F-L-GP  [R402H14]  17.53 21.68 270 top
R2911  0R0603-PAD-2-GP-U  [0R0603-PAD-1-U]  19.43 34.77 90 top
R2912  4K7R2J-2-GP  [R402H16]  17.53 24.35 270 top
R2913  4K7R2J-2-GP  [R402H16]  17.53 25.24 270 top
R2914  0R3J-6-GP  [R603H22]  19.56 31.34 180 bottom
R2915  470KR2J-2-GP  [R402H16]  27.94 35.15 180 bottom
R2916  10KR2J-3-GP  [R402H16]  23.5 37.18 0 top
R2917  0R3J-0-U-GP  [R603H22]  30.48 27.78 0 bottom
R2918  100KR2J-1-GP  [R402H16]  30.1 29.43 270 bottom
R2919  10KR2J-3-GP  [R402H16]  17.14 25.62 0 bottom
R2920  10KR2J-3-GP  [R402H16]  17.4 32.23 180 bottom
R2921  1KR2J-1-GP  [R402H16]  17.53 32.73 270 top
R2922  1KR2J-1-GP  [R402H16]  17.53 31.84 270 top
R2923  0R2J-2-GP  [R402H16]  22.61 35.02 270 top
R3024  15KR2F-GP  [R402H16]  40.51 54.96 180 bottom
R3413  0R0402-PAD-2-GP  [0R0402-PAD-1]  21.34 45.56 90 bottom
R3414  0R0402-PAD-2-GP  [0R0402-PAD-1]  21.34 43.66 90 bottom
R3415  0R0402-PAD-2-GP  [0R0402-PAD-1]  21.34 44.54 90 bottom
R3416  0R0402-PAD-2-GP  [0R0402-PAD-1]  21.34 46.45 90 bottom
R3501  0R0402-PAD-2-GP  [0R0402-PAD-1]  20.07 53.94 270 bottom
R3503  100KR2J-1-GP  [R402H16]  18.03 50.39 0 bottom
R3504  0R0402-PAD-2-GP  [0R0402-PAD-1]  20.07 55.85 270 bottom
R3505  0R0402-PAD-2-GP  [0R0402-PAD-1]  20.07 53.05 270 bottom
R3506  20KR2F-L-GP  [R402H16]  26.8 53.56 90 top
R3507  0R0402-PAD-2-GP  [0R0402-PAD-1]  20.07 54.96 270 bottom
R3508  22K1R2F-L-GP  [R402H16]  26.8 52.67 90 top
R3601  1KR2J-1-GP  [R402H16]  138.81 39.85 270 top
R3602  200KR2F-L-GP  [R402H16]  41 61.84 270 top
R3603  1KR2J-1-GP  [R402H16]  40.01 60.8 270 top
R3607  100KR2J-1-GP  [R402H16]  49.4 96.87 270 top
R3609  0R0402-PAD-2-GP  [0R0402-PAD-1]  42.93 91.03 270 top
R3610  0R0402-PAD-2-GP  [0R0402-PAD-1]  135.76 43.66 90 top
R3611  0R0402-PAD-2-GP  [0R0402-PAD-1]  135.76 42.77 90 top
R3701  1K8R2F-GP  [R402H16]  124.46 32.86 180 top
R3702  2R2F-GP  [R402H16]  120.78 33.24 90 top
R3703  1K8R2F-GP  [R402H16]  139.32 66.77 0 bottom
R3704  0R2J-2-GP  [R402H16]  138.43 66.77 180 bottom
R3706  1K8R2F-GP  [R402H16]  138.43 64.99 0 bottom
R3707  24D9R2F-L-GP  [R402H16]  140.72 67.66 0 bottom
R3708  2R2F-GP  [R402H16]  139.32 64.99 180 bottom
R3709  1K8R2F-GP  [R402H16]  121.28 34.64 180 top
R3710  0R2J-2-GP  [R402H16]  123.57 32.86 180 top
R3711  24D9R2F-L-GP  [R402H16]  120.4 34.64 180 top
R3801  0R5J-5-GP  [R805H24]  73.91 110.46 0 top
R3802  0R0402-PAD-2-GP  [0R0402-PAD-1]  80.01 111.6 270 top
R4301  0R0402-PAD-2-GP  [0R0402-PAD-1]  100.33 25.11 0 bottom
R5201  0R0402-PAD-2-GP  [0R0402-PAD-1]  58.04 90.65 180 bottom
R5202  0R0402-PAD-2-GP  [0R0402-PAD-1]  55.88 94.71 270 top
R5203  100R2J-2-GP  [R402H14]  56.77 91.03 270 bottom
R5204  100R2J-2-GP  [R402H14]  58.29 99.28 180 top
R5205  33R2J-2-GP  [R402H16]  57.4 99.28 180 top
R5223  0R0603-PAD-2-GP-U  [0R0603-PAD-1-U]  32.26 101.19 270 top
R5224  0R2J-2-GP  [R402H16]  73.03 97.76 180 top
R5230  0R0603-PAD-2-GP-U  [0R0603-PAD-1-U]  32.26 102.46 270 top
R5233  0R3J-6-GP  [R603H22]  28.57 95.34 90 top
R5401  0R0402-PAD-2-GP  [0R0402-PAD-1]  15.75 83.53 90 bottom
R5402  0R0402-PAD-2-GP  [0R0402-PAD-1]  15.75 82.64 90 bottom
R5403  0R0402-PAD-2-GP  [0R0402-PAD-1]  15.75 79.98 90 bottom
R5404  0R0402-PAD-2-GP  [0R0402-PAD-1]  15.75 79.09 90 bottom
R5405  0R0402-PAD-2-GP  [0R0402-PAD-1]  15.75 78.2 90 bottom
R5406  0R0402-PAD-2-GP  [0R0402-PAD-1]  15.75 77.31 90 bottom
R5407  0R0402-PAD-2-GP  [0R0402-PAD-1]  15.75 81.76 90 bottom
R5408  0R0402-PAD-2-GP  [0R0402-PAD-1]  15.75 80.87 90 bottom
R5409  0R0603-PAD-2-GP-U  [0R0603-PAD-1-U]  23.62 91.15 270 top
R5410  200KR2F-L-GP  [R402H16]  15.49 74.26 90 bottom
R5411  150KR2F-L-GP  [R402H16]  16.51 71.98 180 bottom
R5412  10KR2J-3-GP  [R402H16]  19.94 70.83 270 bottom
R5413  100KR2J-1-GP  [R402H16]  28.19 91.66 0 top
R5414  150R2J-L1-GP-U  [R402H16]  14.48 83.03 180 bottom
R5415  150R2J-L1-GP-U  [R402H16]  14.48 77.69 180 bottom
R5416  150R2J-L1-GP-U  [R402H16]  14.48 79.47 180 bottom
R5417  150R2J-L1-GP-U  [R402H16]  14.48 81.25 180 bottom
R5418  0R2J-2-GP  [R402H16]  17.02 75.66 0 top
R5419  0R0402-PAD-1-GP  [0R0402-PAD]  19.43 72.1 180 bottom
R5420  10KR2J-3-GP  [R402H16]  18.03 64.61 0 top
R5421  0R0402-PAD-2-GP  [0R0402-PAD-1]  18.41 72.1 0 bottom
R5422  0R0402-PAD-2-GP  [0R0402-PAD-1]  18.03 62.83 180 top
R5423  0R3J-0-U-GP  [R603H22]  23.62 92.55 270 top
R5601  0R0402-PAD-2-GP  [0R0402-PAD-1]  139.06 29.56 270 bottom
R6201  1KR2J-1-GP  [R402H16]  144.02 27.02 90 bottom
R6202  0R0402-PAD-2-GP  [0R0402-PAD-1]  144.02 32.1 180 bottom
R6203  10KR2J-3-GP  [R402H16]  114.55 26.76 0 top
R6204  20KR2F-L-GP  [R402H16]  101.6 22.95 270 bottom
R6205  0R3J-0-U-GP  [R603H22]  28.19 14.83 180 bottom
R6208  100KR2J-1-GP  [R402H16]  20.83 11.02 0 top
R6210  100R3J-4-GP  [R603H22]  120.02 20.54 90 top
R6211  0R3J-0-U-GP  [R603H22]  106.93 26 180 bottom
R6212  0R2J-2-GP  [R402H16]  122.94 24.48 270 top
R6213  0R2J-2-GP  [R402H16]  122.94 26 270 top
R6216  0R0402-PAD-2-GP  [0R0402-PAD-1]  126.87 23.46 270 top
R6401  100KR2J-1-GP  [R402H16]  15.11 72.87 180 bottom
R6601  0R0402-PAD-2-GP  [0R0402-PAD-1]  94.11 104.11 90 top
R6602  100KR2J-1-GP  [R402H16]  106.17 107.66 180 top
R6603  0R2J-2-GP  [R402H16]  107.06 107.66 180 top
R6604  0R0402-PAD-2-GP  [0R0402-PAD-1]  94.11 105 90 top
R6605  1K5R2F-2-GP  [R402H16]  94.87 105.5 90 bottom
R6606  20KR2J-L2-GP  [R402H16]  101.35 98.27 90 top
R6607  0R0603-PAD-2-GP-U  [0R0603-PAD-1-U]  93.09 110.46 90 top
R6608  0R2J-2-GP  [R402H16]  163.7 26 0 top
R6609  10KR2J-3-GP  [R402H16]  95.89 112.49 90 top
R6610  10KR2J-3-GP  [R402H16]  98.68 112.49 90 top
R6611  10KR2J-3-GP  [R402H16]  100.84 112.11 0 top
R6612  10KR2J-3-GP  [R402H16]  99.95 112.11 180 top
R6613  10KR2J-3-GP  [R402H16]  101.73 112.11 0 top
R6614  10KR2J-3-GP  [R402H16]  102.62 112.11 180 top
R6615  10KR2J-3-GP  [R402H16]  104.39 112.11 0 top
R6616  10KR2J-3-GP  [R402H16]  103.5 112.11 180 top
R6617  10KR2J-3-GP  [R402H16]  105.28 112.11 0 top
R6618  10KR2J-3-GP  [R402H16]  106.17 112.11 180 top
R6619  10KR2J-3-GP  [R402H16]  105.28 110.08 180 top
R6620  10KR2J-3-GP  [R402H16]  107.06 112.11 180 top
R6621  0R2J-2-GP  [R402H16]  161.93 26 0 top
R6622  0R0402-PAD-2-GP  [0R0402-PAD-1]  164.47 16.99 0 top
R6623  10KR2J-3-GP  [R402H16]  163.7 23.59 0 top
R6624  0R2J-2-GP  [R402H16]  98.93 107.54 180 bottom
R6625  0R0402-PAD-2-GP  [0R0402-PAD-1]  98.04 107.54 180 bottom
R6626  10KR2J-3-GP  [R402H16]  164.59 23.59 0 top
R6627  0R2J-2-GP  [R402H16]  165.48 23.59 0 top
R6628  0R0402-PAD-2-GP  [0R0402-PAD-1]  162.81 26 0 top
R6629  0R0402-PAD-2-GP  [0R0402-PAD-1]  164.59 26 0 top
R6701  100KR2J-1-GP  [R402H16]  154.18 16.48 270 top
R6702  0R3J-6-GP  [R603H22]  158.62 23.59 180 top
R6705  0R2J-2-GP  [R402H16]  150.11 39.72 270 bottom
R6706  0R2J-2-GP  [R402H16]  161.04 26 180 top
R6707  0R2J-2-GP  [R402H16]  161.16 18.13 180 top
R6708  0R2J-2-GP  [R402H16]  126.24 100.42 90 top
R6709  0R2J-2-GP  [R402H16]  128.02 100.93 90 top
RN401  SRN51J-1-GP  [ARES8-CN24H22]  70.87 38.32 270 bottom
RN1501  SRN2K2J-1-GP  [ARES2H16]  60.45 80.61 180 top
RN1505  SRN10KJ-6-GP  [ARES8-CN24-MUH20]  64.64 86.58 90 bottom
RN1506  SRN10KJ-6-GP  [ARES8-CN24-MUH20]  66.8 84.17 90 bottom
RN1601  SRN10KJ-6-GP  [ARES8-CN24-MUH20]  91.19 92.17 90 bottom
RN1701  SRN10KJ-5-GP  [ARES2H18]  103.25 88.36 180 top
RN1702  SRN0J-6-GP  [SMD-ARES4H20]  92.71 91.79 90 top
RN1703  SRN10KJ-5-GP  [ARES2H18]  98.17 87.85 180 top
RN1801  SRN10KJ-5-GP  [ARES2H18]  76.83 87.98 270 top
RN1802  SRN1KJ-7-GP  [SMD-ARES4H18]  79.63 92.55 180 top
RN1803  SRN10KJ-5-GP  [ARES2H18]  65.91 60.04 270 top
RN1804  SRN10KJ-5-GP  [ARES2H18]  106.3 88.36 180 top
RN1806  SRN0J-7-GP-U  [ARES8-CN24H22]  101.73 71.6 270 top
RN1807  SRN2K2J-4-GP  [ARES8-CN24-UH20]  102.11 83.41 90 top
RN1809  SRN10KJ-6-GP  [ARES8-CN24-MUH20]  88.65 92.17 270 bottom
RN1810  SRN10KJ-5-GP  [ARES2H18]  124.21 97.63 0 top
RN1811  SRN2K2J-1-GP  [ARES2H16]  102.62 85.82 90 top
RN1901  SRN20KJ-1-GP  [SMD-ARES4H20]  100.84 78.2 90 top
RN1902  SRN10KJ-6-GP  [ARES8-CN24-MUH20]  69.09 85.44 90 top
RN2002  SRN10KJ-6-GP  [ARES8-CN24-MUH20]  69.09 89.25 270 top
RN2006  SRN10KJ-5-GP  [ARES2H18]  96.14 82.01 90 top
RN2007  SRN10KJ-5-GP  [ARES2H18]  64.14 82.39 0 bottom
RN2008  SRN2K2J-1-GP  [ARES2H16]  65.28 83.28 180 top
RN2011  SRN10KJ-6-GP  [ARES8-CN24-MUH20]  68.83 82.64 180 top
RN2012  SRN10KJ-6-GP  [ARES8-CN24-MUH20]  88.65 92.17 90 top
RN2401  SRN4K7J-8-GP  [SMD-ARES4H18]  162.81 36.04 180 top
RN2601  -  [0R4P2R-PAD]  144.65 68.42 180 bottom
RN2602  SRN2K2J-1-GP  [ARES2H16]  105.66 91.41 270 top
RN2701  -  [0R4P2R-PAD]  30.23 37.56 90 bottom
RN2901  SRN2K2J-1-GP  [ARES2H16]  24.56 31.51 180 top
RN4301  SRN100J-4-GP  [ARES8-CN24H20]  93.6 22.57 180 top
RN5201  SRN100J-4-GP  [ARES8-CN24H20]  53.14 92.93 180 top
RN5203  SRN100KJ-5-GP  [ARES8-CN24H20]  55.24 98.27 180 top
RN5401  SRN2K2J-1-GP  [ARES2H16]  15.62 75.79 90 bottom
RN5402  SRN470J-3-GP  [ARES8-CN24H20]  18.29 82.26 90 top
RN5403  SRN470J-3-GP  [ARES8-CN24H20]  18.29 78.58 90 top
RN6201  SRN10KJ-5-GP  [ARES2H18]  113.03 26.76 180 top
RN6202  SRN33J-5-GP-U  [SMD-ARES4H18]  111 26.76 180 top
RN6204  SRN2K2J-1-GP  [ARES2H16]  116.08 26.76 180 top
RN6601  SRN2K2J-1-GP  [ARES2H16]  99.44 99.41 0 top
RN6604  -  [0R4P2R-PAD]  91.44 99.03 270 top
SPI25  MX25L6473EM21-10G-GP  [SOIC8-1H86]  139.37 93.54 180 bottom
SPK1  ACES-CON4-29-GP  [50224-0040N-001]  14.8 5.5 180 bottom
SPR1  SPRING-52-GP  [SPR7732H229]  110.8 107 0 bottom
SPR2  SPRING-52-GP  [SPR7732H229]  135.8 65.2 270 bottom
TC1201  ST330U2VDM-4-GP  [CT7343H79]  140.84 60.29 270 bottom
THM261  NCT7718W-GP  [MSOP8-1H44]  82.55 58.64 0 top
TP1  ACES-CON8-40-GP  [50505-0084N-002]  113.8 21 180 bottom
TP402  TPAD14-OP-GP  [TPAD14-OP]  77.83 39.72 180 bottom
TP501  TPAD14-OP-GP  [TPAD14-OP]  90.42 63.09 0 top
TP601  TPAD14-OP-GP  [TPAD14-OP]  95.5 40.23 180 bottom
TP602  TPAD14-OP-GP  [TPAD14-OP]  94.23 40.23 180 bottom
TP603  TPAD14-OP-GP  [TPAD14-OP]  66.93 41.5 180 bottom
TP604  TPAD14-OP-GP  [TPAD14-OP]  68.2 41.5 180 bottom
TP605  TPAD14-OP-GP  [TPAD14-OP]  69.47 55.72 180 bottom
TP606  TPAD14-OP-GP  [TPAD14-OP]  69.47 50.77 180 bottom
TP607  TPAD14-OP-GP  [TPAD14-OP]  68.2 50.77 180 bottom
TP608  TPAD14-OP-GP  [TPAD14-OP]  78.11 43.4 0 top
TP619  TPAD14-OP-GP  [TPAD14-OP]  78.87 70.43 0 top
TP620  TPAD14-OP-GP  [TPAD14-OP]  79.96 72.59 0 top
TP701  TPAD14-OP-GP  [TPAD14-OP]  69.42 46.22 90 bottom
TP702  TPAD14-OP-GP  [TPAD14-OP]  79.35 46.3 90 top
TP703  TPAD14-OP-GP  [TPAD14-OP]  79.88 45.18 0 top
TP704  TPAD14-OP-GP  [TPAD14-OP]  78.36 45.56 0 top
TP705  TPAD14-OP-GP  [TPAD14-OP]  79.76 43.91 0 top
TP801  TPAD14-OP-GP  [TPAD14-OP]  68.58 56.61 90 bottom
TP1501  TPAD14-OP-GP  [TPAD14-OP]  84.71 80.49 0 top
TP1502  TPAD14-OP-GP  [TPAD14-OP]  73.15 74.77 0 top
TP1702  TPAD14-OP-GP  [TPAD14-OP]  84.84 92.17 0 top
TP1703  TPAD14-OP-GP  [TPAD14-OP]  90.65 79.93 0 top
TP1704  TPAD14-OP-GP  [TPAD14-OP]  89.03 79.98 0 top
TP1705  TPAD14-OP-GP  [TPAD14-OP]  87.53 78.02 0 top
TP1706  TPAD14-OP-GP  [TPAD14-OP]  86.36 88.74 180 bottom
TP1707  TPAD14-OP-GP  [TPAD14-OP]  86.36 77.44 0 top
TP1801  TPAD14-OP-GP  [TPAD14-OP]  84.71 87.85 90 bottom
TP1802  TPAD14-OP-GP  [TPAD14-OP]  84.33 85.18 180 bottom
TP1803  TPAD14-OP-GP  [TPAD14-OP]  86.36 87.47 180 bottom
TP1901  TPAD14-OP-GP  [TPAD14-OP]  94.23 38.96 90 bottom
TP1902  TPAD14-OP-GP  [TPAD14-OP]  92.96 76.04 0 top
TP2002  TPAD14-OP-GP  [TPAD14-OP]  88.52 84.17 180 bottom
TP2003  TPAD14-OP-GP  [TPAD14-OP]  75.31 80.49 0 top
TP2004  TPAD14-OP-GP  [TPAD14-OP]  78.99 78.83 0 top
TP2005  TPAD14-OP-GP  [TPAD14-OP]  68.58 79.6 180 bottom
TP2006  TPAD14-OP-GP  [TPAD14-OP]  76.58 84.4 180 bottom
TP2007  TPAD14-OP-GP  [TPAD14-OP]  77.72 78.83 0 top
TP2008  TPAD14-OP-GP  [TPAD14-OP]  82.04 85.18 180 bottom
TP2009  TPAD14-OP-GP  [TPAD14-OP]  75.06 82.39 0 top
TP2014  TPAD14-OP-GP  [TPAD14-OP]  75.36 84.4 180 bottom
TP2015  TPAD14-OP-GP  [TPAD14-OP]  74.68 83.79 0 top
TP2019  TPAD14-OP-GP  [TPAD14-OP]  64.64 79.09 180 bottom
TP2101  TPAD14-OP-GP  [TPAD14-OP]  80.09 70.53 0 top
TP2102  TPAD14-OP-GP  [TPAD14-OP]  82.35 72.36 0 top
TP2103  TPAD14-OP-GP  [TPAD14-OP]  77.22 71.47 0 top
TP2104  TPAD14-OP-GP  [TPAD14-OP]  77.75 69.41 0 top
TP2105  TPAD14-OP-GP  [TPAD14-OP]  83.57 72.36 0 top
TP2106  TPAD14-OP-GP  [TPAD14-OP]  83.31 76.68 0 top
TP2107  TPAD14-OP-GP  [TPAD14-OP]  69.49 72.94 180 bottom
TP2108  TPAD14-OP-GP  [TPAD14-OP]  87.12 73.63 0 top
TP2109  TPAD14-OP-GP  [TPAD14-OP]  83.64 78.38 0 top
TP2201  TPAD14-OP-GP  [TPAD14-OP]  96.77 37.69 180 bottom
TP2202  TPAD14-OP-GP  [TPAD14-OP]  69.47 78.58 180 bottom
TP2203  TPAD14-OP-GP  [TPAD14-OP]  66.29 44.54 180 bottom
TP2204  TPAD14-OP-GP  [TPAD14-OP]  65.91 79.09 180 bottom
TP2205  TPAD14-OP-GP  [TPAD14-OP]  67.06 42.77 180 bottom
TP2206  TPAD14-OP-GP  [TPAD14-OP]  95.76 84.8 180 bottom
TP2207  TPAD14-OP-GP  [TPAD14-OP]  96.27 86.58 180 bottom
TP2208  TPAD14-OP-GP  [TPAD14-OP]  96.77 38.96 180 bottom
TP2408  TPAD14-OP-GP  [TPAD14-OP]  157.48 57.02 0 top
TP2409  TPAD14-OP-GP  [TPAD14-OP]  149.22 62.32 0 top
TP2702  TPAD14-OP-GP  [TPAD14-OP]  26.29 22.32 180 bottom
TP6601  TPAD14-OP-GP  [TPAD14-OP]  93.09 102.96 270 top
TP6602  TPAD14-OP-GP  [TPAD14-OP]  94.61 101.19 270 top
TP6603  TPAD14-OP-GP  [TPAD14-OP]  105.41 101.44 270 top
TP6604  TPAD14-OP-GP  [TPAD14-OP]  106.68 101.44 270 top
TP9601  TPAD14-OP-GP  [TPAD14-OP]  77.83 40.99 180 bottom
TP9602  TPAD14-OP-GP  [TPAD14-OP]  76.58 40.99 180 bottom
TP9611  TPAD14-OP-GP  [TPAD14-OP]  72.64 41.24 0 top
TP9612  TPAD14-OP-GP  [TPAD14-OP]  76.58 39.72 180 bottom
TP9613  TPAD14-OP-GP  [TPAD14-OP]  76.83 44.29 0 top
TP9614  TPAD14-OP-GP  [TPAD14-OP]  75.34 38.5 180 bottom
TP9615  TPAD14-OP-GP  [TPAD14-OP]  76.58 38.45 180 bottom
TP9616  TPAD14-OP-GP  [TPAD14-OP]  76.83 45.56 0 top
TP9617  TPAD14-OP-GP  [TPAD14-OP]  75.36 39.74 180 bottom
TP9618  TPAD14-OP-GP  [TPAD14-OP]  78.11 42.13 0 top
TP9619  TPAD14-OP-GP  [TPAD14-OP]  76.83 43.02 0 top
TP9620  TPAD14-OP-GP  [TPAD14-OP]  84.07 40.99 180 bottom
TP9621  TPAD14-OP-GP  [TPAD14-OP]  69.98 42 0 top
TP9622  TPAD14-OP-GP  [TPAD14-OP]  84.96 36.29 180 bottom
TP9623  TPAD14-OP-GP  [TPAD14-OP]  72.62 39.95 180 bottom
TP9624  TPAD14-OP-GP  [TPAD14-OP]  75.06 40.94 180 bottom
TP9626  TPAD14-OP-GP  [TPAD14-OP]  84.2 45.18 0 top
TP9627  TPAD14-OP-GP  [TPAD14-OP]  84.07 39.72 180 bottom
TP9628  TPAD14-OP-GP  [TPAD14-OP]  83.19 35.91 180 bottom
TP9629  TPAD14-OP-GP  [TPAD14-OP]  81.53 43.91 0 top
TP9630  TPAD14-OP-GP  [TPAD14-OP]  82.93 45.18 0 top
TP9631  TPAD14-OP-GP  [TPAD14-OP]  81.92 35.91 180 bottom
TP9632  TPAD14-OP-GP  [TPAD14-OP]  81.28 39.72 180 bottom
TP9633  TPAD14-OP-GP  [TPAD14-OP]  81.92 37.18 180 bottom
TP9634  TPAD14-OP-GP  [TPAD14-OP]  84.07 37.18 180 bottom
TP9635  TPAD14-OP-GP  [TPAD14-OP]  84.07 38.45 180 bottom
TP9636  TPAD14-OP-GP  [TPAD14-OP]  80.64 35.91 180 bottom
TP9637  TPAD14-OP-GP  [TPAD14-OP]  81.53 45.18 0 top
TP9638  TPAD14-OP-GP  [TPAD14-OP]  81.28 38.32 180 bottom
TP9639  TPAD14-OP-GP  [TPAD14-OP]  81.28 40.99 180 bottom
TP9640  TPAD14-OP-GP  [TPAD14-OP]  80.64 34.64 180 bottom
TP9641  TPAD14-OP-GP  [TPAD14-OP]  80.77 42.89 0 top
TP9642  TPAD14-OP-GP  [TPAD14-OP]  79.38 35.91 180 bottom
TP9643  TPAD14-OP-GP  [TPAD14-OP]  80.64 37.18 180 bottom
TP9644  TPAD14-OP-GP  [TPAD14-OP]  84.33 97 0 top
TP9645  TPAD14-OP-GP  [TPAD14-OP]  92.08 81.76 0 top
TP9646  TPAD14-OP-GP  [TPAD14-OP]  107.95 88.61 0 top
TP9647  TPAD14-OP-GP  [TPAD14-OP]  74.09 39.44 180 bottom
TP9648  TPAD14-OP-GP  [TPAD14-OP]  67.31 45.43 180 bottom
TP9649  TPAD14-OP-GP  [TPAD14-OP]  108.58 89.88 0 top
TP9650  TPAD14-OP-GP  [TPAD14-OP]  69.09 41.12 0 top
TP9651  TPAD14-OP-GP  [TPAD14-OP]  68.33 61.44 180 bottom
TP9652  TPAD14-OP-GP  [TPAD14-OP]  68.33 60.17 180 bottom
TP9653  TPAD14-OP-GP  [TPAD14-OP]  83.44 87.85 180 bottom
TR3401  FILTER-4P-171-GP  [L125100-4PH24]  23.5 59.4 270 bottom
TR3402  FILTER-4P-171-GP  [L125100-4PH24]  25.02 41.24 270 bottom
TR3404  FILTER-4P-171-GP  [L125100-4PH24]  20.45 64.1 270 bottom
TR3405  FILTER-4P-171-GP  [L125100-4PH24]  20.45 61.82 270 bottom
TR5208  FILTER-4P-171-GP  [L125100-4PH24]  60.07 99.54 180 top
U701  74LVC1G07GW-GP  [SC70-5H44]  61.34 46.96 180 bottom
U2101  SLG59M1470VTR-GP  [DFN9J2015H32]  58.93 74.9 180 bottom
U2901  2N7002KDW-GP  [SOT-363H44]  27.56 32.48 180 bottom
U3502  SY6288DAAC-GP  [SOT-23-5H56]  24.77 49.88 90 bottom
U3503  TPS2544RTER-GP  [QFN16-G1D8-UH32]  25.53 54.32 0 bottom
U3601  TPS22966DPUR-GP  [SON14J3020-G2610H34]  32.38 91.28 180 top
U3801  SY6288CCAC-GP  [MSOP8-1H44]  76.96 108.68 180 top
U5201  RT9724GB-GP  [SOT-23-5H51]  51.44 99.54 270 top
U5602  AZ1045-04F-R7G-GP  [DFN10G2510H26]  124.08 27.4 90 bottom
U6601  STM32L151CBU6TR-GP  [QFN48G7-G5D7H26]  99.69 105.5 270 top
U6602  LNG3DMTR-GP  [LGA16-3030-H40]  163.96 20.03 270 top
U6701  LNG3DMTR-GP  [LGA16-3030-H40]  157.99 19.02 90 top
USB1  SKT-USB14-5-GP-U  [SKT-USB14-160155-U]  5.8 62.95 90 bottom
USB2  SKT-USB13-90-GP-U  [SKT-USB13-158172-1]  5.18 44.95 90 bottom
X1801  XTAL-24MHZ-86-GP  [OSC-3225-4P-3H36]  59.82 66.39 180 bottom
X1901  X-32D768KHZ-65-GP  [SMD-OSC2H56]  91.64 95.34 180 bottom
X6601  XTAL-12MHZ-67-GP  [OSC-3225-4P-4H36]  108.97 104.23 90 top

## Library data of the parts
AFTP2601-AFTP2604 AFTP2901-AFTP2904 AFTP2906-AFTP2910 AFTP4201-AFTP4205 AFTP4301-AFTP4310 AFTP4501 AFTP6201-AFTP6203 AFTP6206-AFTP6208 AFTP6210-AFTP6229 AFTP6233 AFTP6235-AFTP6242 AFTP6247 AFTP6248 = AFTE14P-75: tolerance: ZZ.AFT14.101
BATSW1 = NSS507-212F-BAAG1W-A: tolerance: 62.40068.021
BATT1 = C144KA-108A7-L-1: tolerance: 20.81775.008
C701 PC4709-PC4711 PC4714 PC4719-PC4722 PC4729-PC4733 PC4735 PC4738-PC4742 PC4914 = C603H40: tolerance: 78.22610.5BL
C702 C1120 C1121 C1201 C1202 C1204 C1206 C1211 C1218 C1220-C1222 C2605 C3504 C3505 C6602-C6604 C6610 EC701 EC702 EC1707 EC4702 PC4605 PC4801 PC4909 PC4916 PC4918 PC5101 = C402H22: tolerance: 78.10423.2FL
C703 C1101-C1103 C1105 C1109 C1111 C1113 C1116-C1118 C1122 C1212-C1216 C1901 C1902 C2104 C2105 C2109 C2114 C2116 C2128 C2135 C2137 C2138 C2416 C2418 C2901 C3503 PC4601 PC4807 PC5108 PC5109 = C402H22: tolerance: 78.10520.5FL
C1001-C1006 C1108 C1110 C1112 C1115 C1119 C1124 C1125 C2123 C2601 C2702 C2712 C2713 C6703 PC4607 PC4915 = C603H38: tolerance: 78.10610.5BL
C1017 C1018 C1208 C2705 PC4809 = C402H22: tolerance: 78.22510.5FL
C1019 C1020 C2603 C2607 EC8606 EC8617-EC8619 EC8633-EC8638 = C402H22: tolerance: 78.22224.2FL
C1104 C1106 C1107 C1114 C1123 C2142 C2501 C3601 C3605 = C805H54: tolerance: 78.10620.51L
C1203 C2110 C2136 C2147 C2401-C2404 C2406-C2410 C2412 C2414 C2417 C2502 C2602 C2608-C2610 C2612 C2707 C2709 C2710 C2717 C2719 C2720 C3502 C3522 C5401 C5606 C6201 C6202 C6204 C6402 C6701 C6702 PC4902 = C402H22: tolerance: 78.10421.2FL
C1205 C1207 C1209 C2405 C2411 C2413 C5605 EC8620-EC8622 PC4705 = C603H36: tolerance: 78.22523.5BL
C1210 EC1702-EC1706 EC2703-EC2707 EC2901-EC2904 EC4202 EC8601 EC8604 EC8630 EC8631 PC4603 = C402H22: tolerance: 78.10224.2FL
C1601 C1602 C3405-C3408 C5225 C5226 C5229-C5232 = C402H22: tolerance: 78.10423.2FL; signal model: C402H22_SCD1U10V2KX-5GP
C1701 C2415 PC4802 PC4912 = C402H22: tolerance: 78.22124.2FL
C1801 C1802 C6601 C6609 = C402H22: tolerance: 78.15034.1FL
C1903 C1904 = C402H24: tolerance: 78.12034.1FL
C2101 C2503 = C402H22: tolerance: 78.47423.5FL
C2141 C2604 C2701 C2706 C2708 C2711 C2715 C2716 C2718 C2907 C2908 C5214 C5215 PC4524 PC4526 = C603H36: tolerance: 78.47520.5BL
C2421 = C402H22: tolerance: 78.47034.1FL
C2422 C2613 EC2905-EC2908 PC4426 PC4435-PC4437 = C402H22: tolerance: 78.10134.1FL
C2606 = C603H36: tolerance: 78.47134.1BL
C2703 C2704 C3521 C3801 C3802 C6608 PC4911 = C402H22: tolerance: 78.10523.5FL
C2723 EC2708 EC2709 EC5205 EC5206 = C402H22: tolerance: 78.22034.1FL
C2902 C6611 = C603H38: tolerance: 78.10610.L0L
C3404 C3409 = C1206H71: tolerance: 78.10710.52L
C3602 C3603 = C402H22: tolerance: 78.47124.2FL
C3701 C3702 = C402H22: tolerance: 78.22321.2FL
C5202 C5205 PC4804 PC4808 = C805H58: tolerance: 78.47522.L4L
C5203 = C402H22: tolerance: 78.10224.L1L
C5204 C5206 PC4803 = C603H36: tolerance: 78.10424.L0L
C5208 = C402H22: tolerance: 78.10423.L1L
C5209 PC4910 PC4913 = C402H22: tolerance: 78.10520.LAL
C5211 C5212 = C603H36: tolerance: 78.47520.L0L
C5402-C5409 = C402H22: tolerance: 78.10421.2FL; signal model: C402H22_SCD1U16V2KX-3GP
C5602 C5603 C5615 C5616 = C402H22: tolerance: 78.10324.2FL; signal model: C402H22_SCD01U50V2KX-1GP
C6401 = C402H22: tolerance: 78.47321.2FL
C6605-C6607 PC4203-PC4205 PC4402 PC4405 PC4419 PC4531 = C402H22: tolerance: 78.10324.2FL
CPU1 = BGA1168M4024H64: tolerance: 71.HASWE.G0U
D2001 D2401 = SOD323AKH38: tolerance: 83.R2004.G8F
D2402 D2701 D5201 D5202 = SOT23-2D4-312H48: tolerance: 75.00054.E7D
D2501 = SOT-23-9H44: tolerance: 75.00040.07D
D2601 = SOD323AKH44: tolerance: 083.55130.008F
D3602 = SOT23-2D4-312H44: tolerance: 83.00016.K11
D4301-D4303 PD4203 = SOT23-2D8-312H56: tolerance: 75.03101.07D
D5401 = SOT-23-9H44: tolerance: 83.00056.Q11
D6701 = SOT23-2D4-312H48: tolerance: 75.00054.R7D
DB1 = 87212-1002N: tolerance: 20.F1180.010
DCIN1 = 50224-0080N-W02: tolerance: 20.F1295.008
DIMM1 = DS2RK-20401-TP4B-U: tolerance: 62.10024.M31
EC1701 EC2501 EC2502 = C402H22: tolerance: 78.4R774.1FL
EC1801 EC1802 EC1901 EC2503 EC2701 EC4301 EC4302 EC4305 EC4602 = C402H22: tolerance: 78.10034.1FL
EC4201 = C603H40: tolerance: 78.10612.5BL
EC4303 EC5210 EC8602 EC8603 EC8607-EC8616 EC8632 PC4401 PC4412 PC4413 PC4416 PC4418 PC4423 PC4428 PC4429 PC4433 = C402H22: tolerance: 78.10422.5FL
EC4304 EC4701 PC4525 PC4530 = C603H36: tolerance: 78.10424.2BL
EC5207 = C402H22: tolerance: 78.6R864.1FL
EC5211 EC6201-EC6204 = C402H22: tolerance: 78.33034.1FL
EC8605 EC8623-EC8629 PC4201 PC4404 PC4410 PC4417 PC4420 PC4431 PC4432 PC4438 = C603H36: tolerance: 78.10522.5BL
ED1217 = SOD882-10D6-1H20: tolerance: 83.05725.0A0
ED2901-ED2906 = SOD-523-4H28: tolerance: 75.02025.077
EL4201 EL4203 EL4204 R1101 R1105 R2122 R2704 = 0R0805-PAD-1-U: tolerance: ZZ.00PAD.M31
EU3401 EU3403 = LGA9G2310H13: tolerance: 83.3V3U4.0A0
EU3402 EU3404 = SOT-6H58: tolerance: 75.09904.07C
F5201 F5203 = POLYSW-4633-UH43: tolerance: 69.50007.A31
F5202 F6201 = POLYSW-2114H50: tolerance: 69.50007.921
F5204 F5401 = POLYSW-2114H30: tolerance: 69.48001.081
FAN1 SPK1 = 50224-0040N-001: tolerance: 20.F1639.004
G1901 = CON2O-U: tolerance: ZZ.CON2O.XXX
H1 H5 H6 = HOLE335R178: tolerance: ZZ.00PAD.7F1
H2-H4 = HOLE335R229: tolerance: ZZ.00PAD.7G1
HDA27 = QFN48J6-G465H40: tolerance: 71.03234.003
HDD1 = GS12201-1011-9H: tolerance: 20.F1546.020
HDMI1 = SKT-HDMI23-178128-2: tolerance: 22.10296.431
HOMBD1 = AYF531635: tolerance: 020.K0028.0016
HPMIC1 = 2SJ3095-013111F: tolerance: 022.10002.0141
HS1-HS3 = STF237R125H42: tolerance: 34.4GD01.001
IOBD1 = LVD-A40SFYG: tolerance: 20.F2248.040
KB1 = 50588-02601-001-U: tolerance: 20.K0615.026
KBC24 = LQFP128H63: tolerance: 071.00285.000G
KBLIT1 = 50503-0040N-W01: tolerance: 20.K0422.004
L1101 L1102 PR4217 R711 R1102-R1104 R2102 R2108 R2402 R2703 R2706 R2901-R2904 R2906 R2907 R2909 R2911 R5223 R5230 R5409 R6607 = 0R0603-PAD-1-U: tolerance: ZZ.00PAD.M21
L1103 L1104 = L603H40: tolerance: 68.2R21D.10R
LCD1 = LVD-A40SFYG: tolerance: 20.F2037.040
LIDSW1 = SOT23-2D8-123H52: tolerance: 74.05712.0BB
PC4202 PC4516 PC4535 PC4917 = C603H36: tolerance: 78.10422.2BL
PC4206 PC4403 PC4407-PC4409 PC4411 PC4415 PC4425 PC4427 PC4430 PC4434 PC4439-PC4442 PC4509 PC4519 PC4527-PC4529 PC4702-PC4704 PC4906 PC4908 = C805H56: tolerance: 78.10622.51L
PC4406 PC4520 = C603: tolerance: 78.33124.2BL
PC4414 = C402H22: tolerance: 78.47420.8FL
PC4421 = C603H36: tolerance: 78.47322.2BL
PC4422 = C603H38: tolerance: 78.22522.5BL
PC4424 = C402H22: tolerance: 78.10322.2FL
PC4517 PC4518 = C402H20: tolerance: 78.10423.5FL
PC4522 PC4523 = C402H22: tolerance: 78.18034.1FL
PC4536 = C603: tolerance: 78.56124.2BL
PC4602 = C402H22: tolerance: 78.47224.2FL
PC4604 = C402H22: tolerance: 78.47134.1FL
PC4606 = C402H22: tolerance: 78.33420.5FL
PC4608 = C402H22: tolerance: 78.15224.2FL
PC4701 = C402H22: tolerance: 78.82124.2FL
PC4706 = C603H40: tolerance: 78.22422.2BL
PC4707 = C603H38: tolerance: 078.15422.02B1
PC4708 = C603H36: tolerance: 78.10225.2BL
